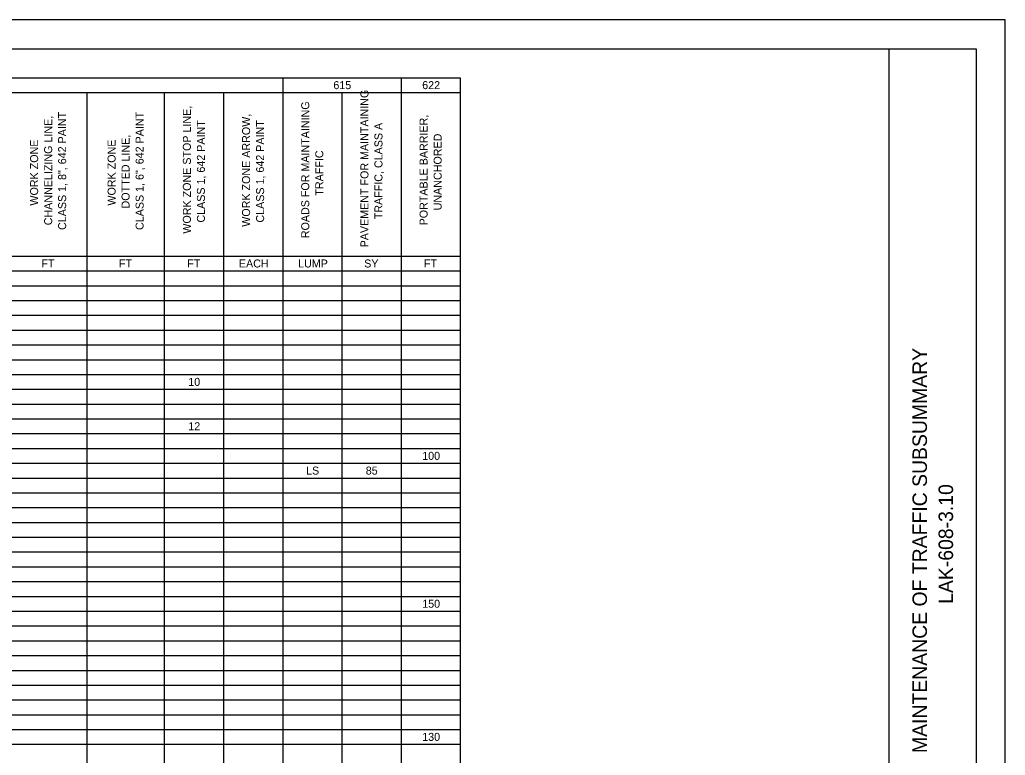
# Model space of a CAD drawing. Extents: x 0 to 34, y 0 to 22.
# Drawn here: x 17.01 to 34, y 9.32 to 22 of the extents above; entities that cross this region are included whole.
import ezdxf

# ---------------------------------------------------------------- set-up
doc = ezdxf.new("R2010")
doc.units = 0
for name, color, linetype in [('SH_Border', 7, 'Continuous'), ('SH_Cut_Line', 7, 'Continuous'), ('SH_Data', 7, 'Continuous'), ('SH_Text', 7, 'Continuous')]:
    doc.layers.add(name, color=color, linetype=linetype)

msp = doc.modelspace()

# ---------------------------------------------------------------- linework, layer by layer
at = {"layer": 'SH_Border'}
msp.add_line((32, 0.5), (32, 21.5), dxfattribs=at)
msp.add_lwpolyline([(1.5, 21.5), (33.5, 21.5), (33.5, 0.5), (1.5, 0.5)], close=True, dxfattribs=at)
at = {"layer": 'SH_Cut_Line'}
msp.add_lwpolyline([(0, 0), (34, 0), (34, 22), (0, 22)], close=True, dxfattribs=at)
at = {"layer": 'SH_Text'}
for p, q in [((2, 21), (24.605, 21)), ((21.545, 21), (21.545, 5.175)), ((23.585, 21), (23.585, 5.175)), ((24.605, 21), (24.605, 5.175)), ((8.045, 20.745), (24.605, 20.745)), ((18.17, 20.745), (18.17, 5.175)), ((19.505, 20.745), (19.505, 5.175)), ((20.525, 20.745), (20.525, 5.175)), ((22.565, 20.745), (22.565, 5.175)), ((8.045, 17.925), (24.605, 17.925)), ((2, 17.67), (24.605, 17.67)), ((2, 17.415), (24.605, 17.415)), ((2, 17.16), (24.605, 17.16)), ((2, 16.905), (24.605, 16.905)), ((2, 16.65), (24.605, 16.65)), ((2, 16.395), (24.605, 16.395)), ((2, 16.14), (24.605, 16.14)), ((2, 15.885), (24.605, 15.885)), ((2, 15.63), (24.605, 15.63)), ((2, 15.375), (24.605, 15.375)), ((2, 15.12), (24.605, 15.12)), ((2, 14.865), (24.605, 14.865)), ((2, 14.61), (24.605, 14.61)), ((2, 14.355), (24.605, 14.355)), ((2, 14.1), (24.605, 14.1)), ((2, 13.845), (24.605, 13.845)), ((2, 13.59), (24.605, 13.59)), ((2, 13.335), (24.605, 13.335)), ((2, 13.08), (24.605, 13.08)), ((2, 12.825), (24.605, 12.825)), ((2, 12.57), (24.605, 12.57)), ((2, 12.315), (24.605, 12.315)), ((2, 12.06), (24.605, 12.06)), ((2, 11.805), (24.605, 11.805)), ((2, 11.55), (24.605, 11.55)), ((2, 11.295), (24.605, 11.295)), ((2, 11.04), (24.605, 11.04)), ((2, 10.785), (24.605, 10.785)), ((2, 10.53), (24.605, 10.53)), ((2, 10.275), (24.605, 10.275)), ((2, 10.02), (24.605, 10.02)), ((2, 9.765), (24.605, 9.765)), ((2, 9.51), (24.605, 9.51))]:
    msp.add_line(p, q, dxfattribs=at)

# ---------------------------------------------------------------- texts
at = {"layer": 'SH_Data'}
for s, p in [('MAINTENANCE OF TRAFFIC SUBSUMMARY', (32.65, 9.359)), ('LAK-608-3.10', (33.1, 11.931))]:
    msp.add_text(s, height=0.25, rotation=90, dxfattribs=at).set_placement(p)
at = {"layer": 'SH_Text'}
for s, p in [('615', (22.419, 20.803)), ('622', (23.95, 20.803)), ('FT', (17.388, 17.729)), ('FT', (18.723, 17.729)), ('FT', (19.9, 17.729)), ('EACH', (20.791, 17.729)), ('LUMP', (21.811, 17.729)), ('SY', (22.95, 17.729)), ('FT', (23.98, 17.729)), ('10', (19.918, 15.688)), ('12', (19.918, 14.923)), ('100', (23.95, 14.413)), ('LS', (21.949, 14.159)), ('85', (22.977, 14.159)), ('150', (23.95, 11.864)), ('130', (23.95, 9.569))]:
    msp.add_text(s, height=0.138, dxfattribs=at).set_placement(p)
for s, p in [('PAVEMENT FOR MAINTAINING ', (23.023, 18.076)), ('ROADS FOR MAINTAINING ', (22.003, 18.234)), ('CLASS 1, 8", 642 PAINT', (17.813, 18.376)), ('CLASS 1, 6", 642 PAINT', (19.148, 18.376)), ('WORK ZONE STOP LINE, ', (19.963, 18.312)), ('CHANNELIZING LINE,', (17.572, 18.457)), ('CLASS 1, 642 PAINT', (20.205, 18.503)), ('WORK ZONE ARROW, ', (20.983, 18.431)), ('CLASS 1, 642 PAINT', (21.225, 18.503)), ('TRAFFIC, CLASS A', (23.265, 18.561)), ('PORTABLE BARRIER, ', (24.043, 18.455)), ('WORK ZONE', (17.33, 18.796)), ('WORK ZONE', (18.665, 18.796)), ('DOTTED LINE,', (18.906, 18.746)), ('UNANCHORED', (24.285, 18.714)), ('TRAFFIC', (22.245, 18.968))]:
    msp.add_text(s, height=0.138, rotation=90, dxfattribs=at).set_placement(p)

doc.saveas('drawing.dxf')
